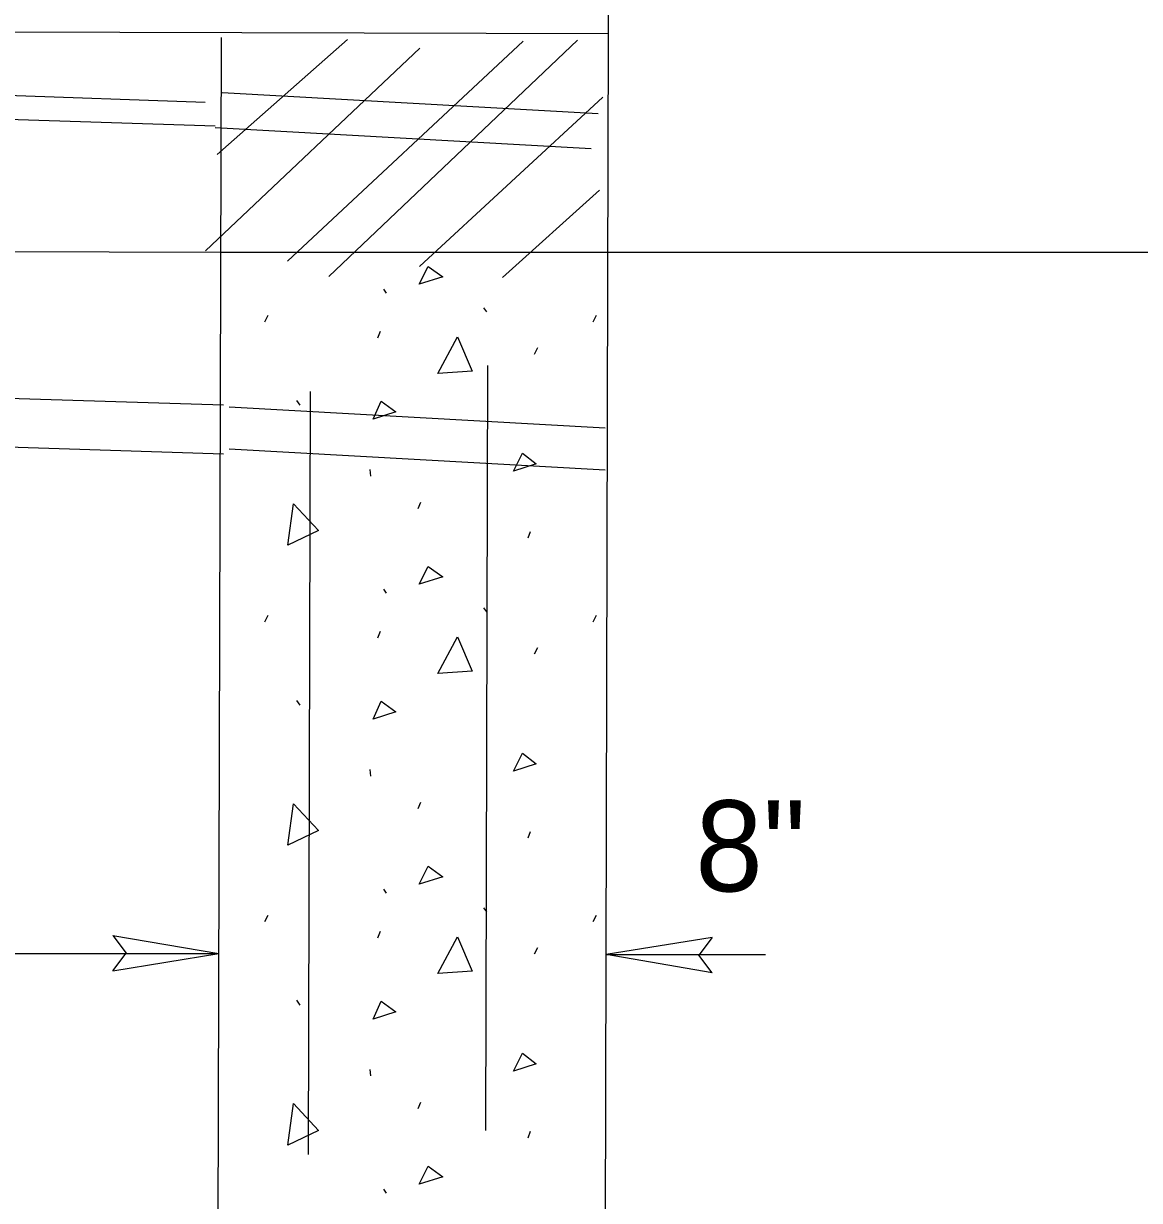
# Model space of a CAD drawing. Extents: x 4.74 to 11.91, y -5.26 to 4.54.
# Drawn here: x 8.231 to 8.968, y -0.077 to 0.7 of the extents above; entities that cross this region are included whole.
import ezdxf

# ---------------------------------------------------------------- set-up
doc = ezdxf.new("R2010")
doc.units = 0
for name, color, linetype in [('DETL-DIMS', 7, 'Continuous'), ('DETL-LINE', 7, 'Continuous'), ('DETL-NOTE', 7, 'Continuous'), ('DETL-PATT', 7, 'Continuous')]:
    doc.layers.add(name, color=color, linetype=linetype)

msp = doc.modelspace()

# ---------------------------------------------------------------- linework, layer by layer
at = {"layer": 'DETL-DIMS'}
for p, q in [((8.61692, 0.54879), (9.46079, 0.54879)), ((8.29017, 0.09783), (8.36013, 0.08604)), ((8.29017, 0.09783), (8.29887, 0.08617)), ((8.68579, 0.09663), (8.61571, 0.08537)), ((8.68579, 0.09663), (8.67696, 0.085)), ((6.34554, 0.08604), (8.36013, 0.08604)), ((8.29008, 0.0745), (8.29887, 0.08617)), ((8.29008, 0.0745), (8.36013, 0.08604)), ((8.68562, 0.07329), (8.61571, 0.08537)), ((8.61571, 0.08537), (8.72083, 0.08537)), ((8.68562, 0.07329), (8.67696, 0.085))]:
    msp.add_line(p, q, dxfattribs=at)
at = {"layer": 'DETL-LINE'}
for p, q in [((8.61729, 0.69304), (8.61729, 0.9945)), ((6.353, 0.69621), (8.35775, 0.63221)), ((7.50208, 0.696), (8.61729, 0.69304)), ((8.61688, 0.53146), (8.61729, 0.69304)), ((8.36133, 0.53412), (8.36175, 0.69033)), ((7.50429, 0.67767), (8.35096, 0.64771)), ((8.61037, 0.63996), (8.36229, 0.65379)), ((8.60579, 0.61692), (8.35771, 0.63075)), ((6.34687, 0.55412), (8.36137, 0.54879)), ((8.36137, 0.54879), (8.61692, 0.54879)), ((8.35712, -1.05021), (8.36133, 0.53412)), ((8.612, -1.30979), (8.61688, 0.53146)), ((6.35267, 0.51092), (8.36308, 0.44804)), ((6.35267, 0.47867), (8.36308, 0.41579)), ((8.53746, 0.47408), (8.53613, -0.03079)), ((8.42042, 0.45687), (8.41908, -0.0465)), ((8.615, 0.43258), (8.36692, 0.44642)), ((8.615, 0.40496), (8.36692, 0.41879))]:
    msp.add_line(p, q, dxfattribs=at)
at = {"layer": 'DETL-PATT'}
for p, q in [((8.35129, 0.54967), (8.49283, 0.68333)), ((8.44508, 0.68912), (8.35908, 0.61313)), ((8.4055, 0.54283), (8.56104, 0.68792)), ((8.43279, 0.53271), (8.59687, 0.68871)), ((8.49258, 0.53933), (8.61358, 0.65112)), ((8.54729, 0.532), (8.61129, 0.58962)), ((8.46886, 0.52436), (8.47047, 0.52167)), ((8.39049, 0.50289), (8.39264, 0.50718)), ((8.53469, 0.51201), (8.53684, 0.50933)), ((8.60716, 0.50289), (8.6093, 0.50718)), ((8.4651, 0.4923), (8.46671, 0.4966)), ((8.56851, 0.48157), (8.57066, 0.48586)), ((8.41142, 0.45097), (8.41357, 0.44775)), ((8.45973, 0.40535), (8.46027, 0.40105)), ((8.49175, 0.37958), (8.49336, 0.38387)), ((8.56422, 0.36026), (8.56583, 0.36455)), ((8.46886, 0.32644), (8.47047, 0.32376)), ((8.53469, 0.3141), (8.53684, 0.31141)), ((8.39049, 0.30497), (8.39264, 0.30926)), ((8.60716, 0.30497), (8.6093, 0.30926)), ((8.4651, 0.29438), (8.46671, 0.29868)), ((8.56851, 0.28365), (8.57066, 0.28794)), ((8.41142, 0.25305), (8.41357, 0.24983)), ((8.45973, 0.20743), (8.46027, 0.20313)), ((8.49175, 0.18166), (8.49336, 0.18596)), ((8.56422, 0.16234), (8.56583, 0.16663)), ((8.46886, 0.12852), (8.47047, 0.12584)), ((8.39049, 0.10705), (8.39264, 0.11135)), ((8.53469, 0.11618), (8.53684, 0.11349)), ((8.60716, 0.10705), (8.6093, 0.11135)), ((8.4651, 0.09647), (8.46671, 0.10076)), ((8.56851, 0.08573), (8.57066, 0.09003)), ((8.41142, 0.05514), (8.41357, 0.05192)), ((8.45973, 0.00951), (8.46027, 0.00522)), ((8.49175, -0.01625), (8.49336, -0.01196)), ((8.56422, -0.03558), (8.56583, -0.03128)), ((8.46886, -0.06939), (8.47047, -0.07208))]:
    msp.add_line(p, q, dxfattribs=at)
for points in [[(8.49229, 0.52758), (8.49819, 0.53939), (8.50786, 0.53241), (8.49229, 0.52758)], [(8.50463, 0.46868), (8.51752, 0.49284), (8.52718, 0.47029), (8.50463, 0.46868)], [(8.46188, 0.43862), (8.46725, 0.45043), (8.47691, 0.44346), (8.46188, 0.43862)], [(8.55455, 0.40427), (8.56046, 0.41608), (8.56958, 0.4091), (8.55455, 0.40427)], [(8.40552, 0.35543), (8.40928, 0.3828), (8.42592, 0.36509), (8.40552, 0.35543)], [(8.49229, 0.32966), (8.49819, 0.34147), (8.50786, 0.33449), (8.49229, 0.32966)], [(8.50463, 0.27077), (8.51752, 0.29492), (8.52718, 0.27238), (8.50463, 0.27077)], [(8.46188, 0.24071), (8.46725, 0.25252), (8.47691, 0.24554), (8.46188, 0.24071)], [(8.55455, 0.20635), (8.56046, 0.21816), (8.56958, 0.21119), (8.55455, 0.20635)], [(8.40552, 0.15751), (8.40928, 0.18488), (8.42592, 0.16717), (8.40552, 0.15751)], [(8.49229, 0.13174), (8.49819, 0.14355), (8.50786, 0.13658), (8.49229, 0.13174)], [(8.50463, 0.07285), (8.51752, 0.097), (8.52718, 0.07446), (8.50463, 0.07285)], [(8.46188, 0.04279), (8.46725, 0.0546), (8.47691, 0.04762), (8.46188, 0.04279)], [(8.55455, 0.00844), (8.56046, 0.02025), (8.56958, 0.01327), (8.55455, 0.00844)], [(8.40552, -0.04041), (8.40928, -0.01303), (8.42592, -0.03075), (8.40552, -0.04041)], [(8.49229, -0.06617), (8.49819, -0.05436), (8.50786, -0.06134), (8.49229, -0.06617)]]:
    msp.add_lwpolyline(points, dxfattribs=at)

# ---------------------------------------------------------------- texts
at = {"layer": 'DETL-NOTE'}
msp.add_text('8"', height=0.06, dxfattribs=at).set_placement((8.6745, 0.12704))

doc.saveas('drawing.dxf')
